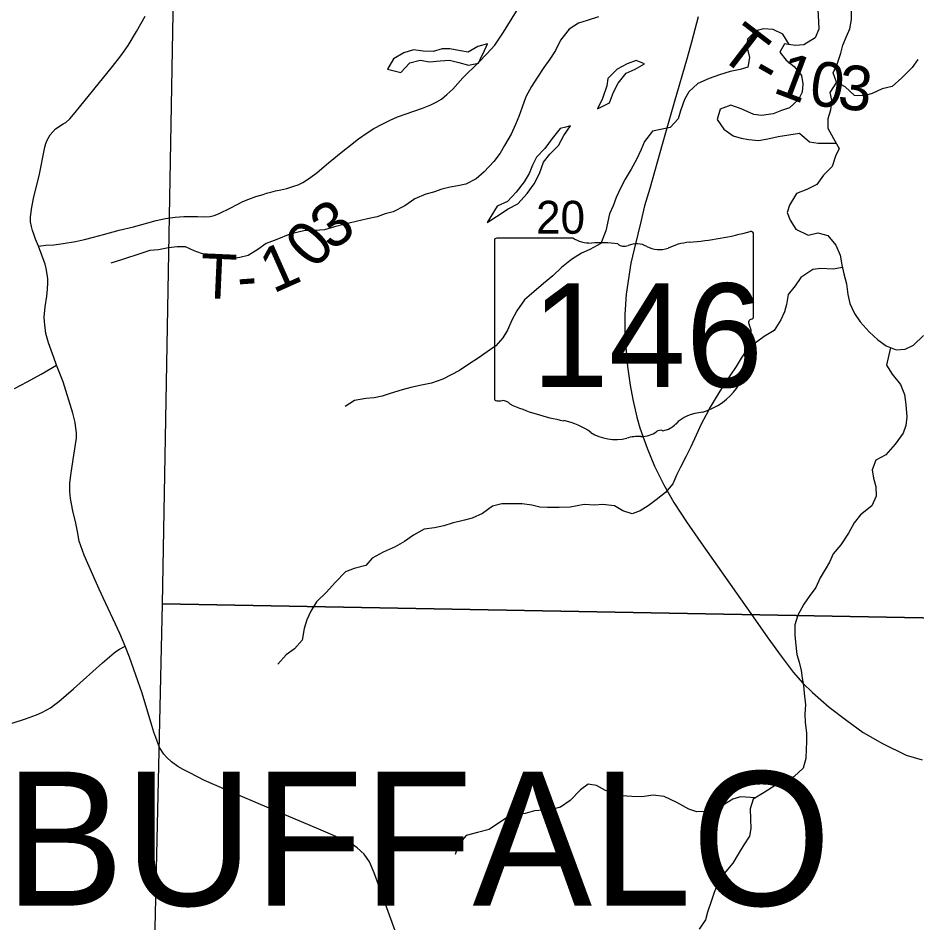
# Model space of a CAD drawing. Extents: x 0 to 34, y 0 to 22.
# Drawn here: x 27.9 to 29.042, y 16.225 to 17.376 of the extents above; entities that cross this region are included whole.
import ezdxf

# ---------------------------------------------------------------- set-up
doc = ezdxf.new("R2010")
doc.units = 0
for name, color, linetype in [('GM_X_Corporation', 7, 'Continuous'), ('GM_X_County_Road', 7, 'Continuous'), ('GM_X_Minor_Lake', 7, 'Continuous'), ('GM_X_Minor_River', 7, 'Continuous'), ('GM_X_Section_Text', 7, 'Continuous'), ('GM_X_State_Location', 7, 'Continuous'), ('GM_X_State_Route', 7, 'Continuous'), ('GM_X_State_Shield', 7, 'Continuous'), ('GM_X_Township_Road', 7, 'Continuous'), ('GM_X_Township_Road_Text', 7, 'Continuous'), ('GM_X_Township_Text', 7, 'Continuous')]:
    doc.layers.add(name, color=color, linetype=linetype)

msp = doc.modelspace()

# ---------------------------------------------------------------- linework, layer by layer
at = {"layer": 'GM_X_Corporation'}
for points in [[(28.101, 17.617), (29.1032, 17.5952), (29.0727, 16.6129), (28.0831, 16.631)], [(28.0831, 16.631), (29.0727, 16.6129), (29.0554, 15.5858), (28.0603, 15.6194)]]:
    msp.add_lwpolyline(points, close=True, dxfattribs=at)
at = {"layer": 'GM_X_County_Road'}
for points in [[(28.0356, 16.5774), (28.0289, 16.5933), (28.0203, 16.6117), (28.0079, 16.6387), (28.0027, 16.65), (27.9975, 16.6614), (27.9834, 16.6931), (27.9773, 16.7107), (27.9749, 16.723), (27.973, 16.7337), (27.9692, 16.7493), (27.9662, 16.7652), (27.9653, 16.7737), (27.9655, 16.7846), (27.9671, 16.7976), (27.9706, 16.8203), (27.9737, 16.8418), (27.9739, 16.8486), (27.9731, 16.8546), (27.9721, 16.8616), (27.9692, 16.8734), (27.9567, 16.9132), (27.9485, 16.9348), (27.9452, 16.9445), (27.9381, 16.9632), (27.9364, 16.969), (27.9349, 16.9748), (27.9334, 16.9858), (27.933, 16.99), (27.9328, 16.9955), (27.934, 17.0089), (27.9362, 17.0225), (27.937, 17.0313), (27.9373, 17.0393), (27.9373, 17.0445), (27.9364, 17.0503), (27.9353, 17.0575), (27.9338, 17.0632), (27.9254, 17.0861), (27.9217, 17.0949), (27.9196, 17.1012), (27.9179, 17.1057), (27.9166, 17.111), (27.9155, 17.1169), (27.9153, 17.1233), (27.917, 17.1354), (27.9197, 17.1485), (27.9265, 17.1755), (27.9336, 17.2119), (27.9347, 17.2164), (27.9365, 17.2208), (27.9403, 17.2273), (27.9437, 17.2312), (27.9472, 17.2352), (27.957, 17.2413), (27.9602, 17.2432), (27.9655, 17.2479), (27.9721, 17.2557), (28.0198, 17.3142), (28.0304, 17.3278), (28.0395, 17.341), (28.05, 17.359), (28.0611, 17.3783)], [(27.8919, 16.4794), (27.9088, 16.485), (27.923, 16.4901), (27.9299, 16.493), (27.9361, 16.4962), (27.9408, 16.499), (27.9446, 16.5017), (27.9514, 16.507), (27.9702, 16.5232), (28.0069, 16.5563), (28.0216, 16.5689), (28.0251, 16.5713), (28.0283, 16.5734), (28.0356, 16.5774)], [(28.3789, 16.2152), (28.3629, 16.26), (28.3524, 16.289), (28.3462, 16.3032), (28.3395, 16.3128), (28.3307, 16.321), (28.3249, 16.325), (28.3166, 16.3293), (28.2997, 16.3371), (28.2819, 16.3445), (28.2187, 16.3715), (28.1651, 16.3942), (28.1366, 16.4065), (28.1179, 16.4161), (28.1096, 16.4205), (28.1028, 16.4244), (28.0946, 16.4301), (28.0886, 16.4357), (28.0849, 16.4402), (28.0793, 16.4486), (28.0745, 16.4613), (28.0723, 16.4681), (28.0698, 16.4765), (28.0572, 16.5177), (28.0411, 16.5633), (28.0356, 16.5774)]]:
    msp.add_lwpolyline(points, dxfattribs=at)
at = {"layer": 'GM_X_Minor_Lake'}
for points in [[(28.4894, 17.3278), (28.4909, 17.3309), (28.4965, 17.343), (28.4841, 17.3396), (28.4719, 17.3324), (28.4621, 17.3344), (28.4485, 17.337), (28.4387, 17.3367), (28.4273, 17.3333), (28.4145, 17.3337), (28.4024, 17.3356), (28.3899, 17.3318), (28.377, 17.3239), (28.3694, 17.311)], [(28.3694, 17.311), (28.3861, 17.3068), (28.3978, 17.3189), (28.411, 17.3223), (28.4228, 17.3204), (28.4364, 17.3215), (28.4481, 17.3222), (28.4598, 17.3196), (28.4723, 17.3162), (28.4848, 17.3184), (28.4894, 17.3278)], [(28.6919, 17.3195), (28.6856, 17.3219), (28.6742, 17.3178), (28.6614, 17.311), (28.6496, 17.2992), (28.6481, 17.2898), (28.6428, 17.2735), (28.6363, 17.2606)], [(28.6363, 17.2606), (28.6514, 17.2682), (28.6568, 17.2818), (28.6628, 17.2932), (28.6727, 17.306), (28.6844, 17.3109), (28.6962, 17.3178), (28.6919, 17.3195)], [(28.4961, 17.116), (28.5078, 17.1236), (28.5226, 17.1334), (28.5351, 17.1398), (28.5469, 17.1527), (28.5556, 17.1652), (28.5624, 17.1781), (28.5677, 17.1928), (28.5757, 17.2027), (28.5867, 17.2137), (28.5935, 17.2265), (28.6018, 17.2387), (28.5961, 17.2373)], [(28.5961, 17.2373), (28.589, 17.2356), (28.5787, 17.2228), (28.5693, 17.2099), (28.5587, 17.1989), (28.5537, 17.1887), (28.5495, 17.1781), (28.5431, 17.1675), (28.5329, 17.1546), (28.5219, 17.1429), (28.5086, 17.1368), (28.4961, 17.116)]]:
    msp.add_lwpolyline(points, dxfattribs=at)
at = {"layer": 'GM_X_Minor_River'}
for points in [[(28.9167, 17.3864), (28.9175, 17.3717), (28.9178, 17.3618), (28.9129, 17.3508), (28.8989, 17.3417), (28.8875, 17.341), (28.8743, 17.3433), (28.8682, 17.3327), (28.8762, 17.3224), (28.8864, 17.3145), (28.8958, 17.3027), (28.8973, 17.2925), (28.8965, 17.2819), (28.892, 17.2724), (28.8806, 17.2618), (28.8704, 17.2584), (28.8598, 17.2542), (28.845, 17.252), (28.8352, 17.2535), (28.8189, 17.2607), (28.8057, 17.2653), (28.7921, 17.26), (28.7887, 17.2471), (28.797, 17.2346), (28.8087, 17.2263), (28.8189, 17.2232), (28.8287, 17.2217), (28.8412, 17.2201), (28.8529, 17.2224), (28.8661, 17.2254), (28.8798, 17.2273), (28.8934, 17.2296), (28.9058, 17.2185), (28.9168, 17.217), (28.9397, 17.217)], [(28.9404, 17.2943), (28.9359, 17.3061), (28.9416, 17.3186), (28.9458, 17.3311), (28.9484, 17.3413), (28.953, 17.3523), (28.9572, 17.3621), (28.9591, 17.3739), (28.9591, 17.3875)], [(28.6377, 17.3773), (28.6233, 17.3728), (28.6123, 17.3694), (28.6002, 17.3619), (28.5892, 17.3478), (28.5831, 17.3346), (28.5759, 17.3236), (28.568, 17.313), (28.5592, 17.2994), (28.5524, 17.2888), (28.5452, 17.2759), (28.5406, 17.2626), (28.5361, 17.2509), (28.5319, 17.2406), (28.5266, 17.2285), (28.5182, 17.2141), (28.5125, 17.2043), (28.5046, 17.1937), (28.4921, 17.1804), (28.4822, 17.1717), (28.469, 17.1649), (28.4588, 17.1627), (28.4489, 17.1608), (28.4383, 17.1585), (28.4277, 17.1544), (28.4179, 17.1521), (28.4039, 17.146), (28.3914, 17.1373), (28.3766, 17.1294), (28.3664, 17.1271), (28.3562, 17.1234), (28.3437, 17.1207), (28.315, 17.1139), (28.3021, 17.1105), (28.2892, 17.1068), (28.2775, 17.106), (28.2647, 17.1057), (28.245, 17.1012)], [(28.8802, 17.3423), (28.8721, 17.3554), (28.8596, 17.3615), (28.8475, 17.3623), (28.8377, 17.3596), (28.8271, 17.349), (28.8263, 17.3396), (28.8297, 17.3259), (28.8277, 17.3134), (28.8179, 17.3104), (28.805, 17.3081), (28.7914, 17.3036), (28.7782, 17.2991), (28.7638, 17.2926), (28.7524, 17.2821), (28.7471, 17.2722), (28.7418, 17.2578), (28.7391, 17.248), (28.7289, 17.2366), (28.7187, 17.2347), (28.7062, 17.2321), (28.6963, 17.2188), (28.6918, 17.2086), (28.6861, 17.1961), (28.6793, 17.1836), (28.6717, 17.1711), (28.666, 17.1605), (28.6599, 17.1476), (28.6561, 17.137), (28.6515, 17.1272), (28.647, 17.1054)], [(29.0437, 17.3234), (29.0365, 17.3131), (29.0232, 17.2999), (29.0111, 17.2889), (28.9982, 17.2859), (28.9857, 17.2802), (28.9759, 17.2772), (28.9631, 17.2776), (28.9514, 17.2886), (28.9404, 17.2943), (28.9317, 17.2811), (28.9339, 17.2716), (28.9328, 17.2587), (28.9293, 17.2477), (28.9293, 17.2359), (28.9365, 17.2227), (28.9436, 17.2102), (28.9391, 17.2003), (28.9349, 17.1874), (28.9239, 17.1761), (28.9152, 17.1643), (28.9027, 17.1579), (28.8895, 17.153), (28.8803, 17.1382), (28.8777, 17.1288), (28.8814, 17.1189), (28.8886, 17.1075)], [(28.8886, 17.1075), (28.904, 17.0998), (28.9164, 17.1029), (28.9293, 17.0995), (28.9396, 17.0871), (28.9449, 17.0746), (28.9472, 17.0621), (28.9495, 17.0507), (28.953, 17.0378), (28.9545, 17.0246), (28.9572, 17.0132), (28.9633, 17.0003), (28.9702, 16.9898), (28.9819, 16.9769), (28.993, 16.9667), (29.0032, 16.9592), (29.0161, 16.9543), (29.0274, 16.9551), (29.038, 16.96), (29.0509, 16.9722)], [(28.245, 17.1012), (28.2285, 17.0944), (28.2149, 17.0895), (28.2043, 17.0818), (28.1922, 17.0742), (28.1816, 17.0715), (28.1684, 17.0692), (28.1555, 17.0714), (28.1438, 17.074), (28.1328, 17.0766), (28.1233, 17.08), (28.1123, 17.0849), (28.1017, 17.0849), (28.0907, 17.0837), (28.0779, 17.0814), (28.0669, 17.0802), (28.0567, 17.0771), (28.0309, 17.0687), (28.0173, 17.0641)], [(28.647, 17.1054), (28.6405, 17.0891), (28.6265, 17.0818), (28.6159, 17.0768), (28.6034, 17.0688), (28.5906, 17.0586), (28.5796, 17.0483), (28.5675, 17.0384), (28.5555, 17.0277), (28.5434, 17.0175), (28.5339, 17.0038), (28.5275, 16.992), (28.5219, 16.9791), (28.5159, 16.9692), (28.5072, 16.9593), (28.4959, 16.9517), (28.4845, 16.9433), (28.4739, 16.9369), (28.4607, 16.9277), (28.4395, 16.917), (28.4252, 16.9117), (28.4127, 16.909), (28.3991, 16.9063), (28.3881, 16.9032), (28.3726, 16.8986), (28.3624, 16.8951), (28.3525, 16.8932), (28.3419, 16.8924), (28.3272, 16.8897), (28.3155, 16.8821)], [(28.9479, 17.0587), (28.9359, 17.0567), (28.9204, 17.0574), (28.9101, 17.0563), (28.895, 17.046), (28.8875, 17.0353), (28.8788, 17.0243), (28.8766, 17.0118), (28.8743, 17.0023), (28.8694, 16.9924), (28.8608, 16.9788), (28.8483, 16.9711), (28.8385, 16.9639), (28.8271, 16.9555), (28.8192, 16.9434), (28.8128, 16.9331), (28.8045, 16.921), (28.794, 16.905), (28.7861, 16.8917), (28.7797, 16.8811), (28.7744, 16.8716), (28.768, 16.8594), (28.762, 16.8458), (28.7552, 16.8306), (28.7488, 16.818), (28.742, 16.8051), (28.7371, 16.7956), (28.7322, 16.7839), (28.7228, 16.7725), (28.7111, 16.7633), (28.7009, 16.7557), (28.6907, 16.7496), (28.6805, 16.7454), (28.6687, 16.7495), (28.6581, 16.7556), (28.643, 16.7574), (28.6324, 16.7566), (28.6195, 16.7573), (28.6017, 16.7542), (28.5877, 16.7538), (28.5729, 16.7537), (28.5631, 16.7541), (28.5528, 16.7567), (28.5407, 16.7582), (28.5248, 16.7585), (28.5146, 16.7585), (28.5029, 16.7554), (28.49, 16.7459), (28.4768, 16.7401), (28.467, 16.7374), (28.4514, 16.7336), (28.4408, 16.7302), (28.4291, 16.7278), (28.4159, 16.7259), (28.4023, 16.7186), (28.3909, 16.7103), (28.3792, 16.7038), (28.3637, 16.6969), (28.3497, 16.6893), (28.3418, 16.6798), (28.3267, 16.6759), (28.3161, 16.6717), (28.3029, 16.6584), (28.2919, 16.6458), (28.2791, 16.6337), (28.2719, 16.6219), (28.2667, 16.6109), (28.2633, 16.5999), (28.2607, 16.5851), (28.2509, 16.5741), (28.2403, 16.5661), (28.2297, 16.5546)], [(29.0087, 16.9571), (29.004, 16.9345), (29.0109, 16.9232), (29.0215, 16.91), (29.0265, 16.8975), (29.0284, 16.8846), (29.0296, 16.8687), (29.0285, 16.8577), (29.0251, 16.8482), (29.0149, 16.8341), (29.0028, 16.8204), (28.9904, 16.8136), (28.9855, 16.8014), (28.9874, 16.7908), (28.9901, 16.7802), (28.9905, 16.7681), (28.9852, 16.7559), (28.9709, 16.7445), (28.9626, 16.7342), (28.9554, 16.721), (28.9456, 16.7061), (28.9362, 16.6947), (28.9313, 16.6841), (28.9257, 16.6746), (28.9196, 16.6644), (28.914, 16.6518), (28.9053, 16.6404), (28.8985, 16.6309), (28.891, 16.6169), (28.8872, 16.6044), (28.8873, 16.5918), (28.8881, 16.5824), (28.89, 16.5668), (28.8927, 16.557), (28.8954, 16.5464), (28.8965, 16.5365), (28.8981, 16.5271), (28.8992, 16.5176), (28.9008, 16.5028), (28.9001, 16.4914), (28.9005, 16.4804), (28.902, 16.4672), (28.9021, 16.4558), (28.9017, 16.4463), (28.9014, 16.4346), (28.898, 16.4224), (28.8863, 16.4114), (28.8753, 16.4061), (28.8636, 16.4011), (28.8481, 16.3912), (28.8341, 16.3828), (28.8304, 16.3703), (28.8308, 16.3574), (28.8312, 16.3453), (28.8297, 16.3358), (28.8222, 16.3248), (28.815, 16.313), (28.8086, 16.3016), (28.7973, 16.2883), (28.7894, 16.2761), (28.7845, 16.264), (28.7811, 16.2541), (28.7762, 16.2393), (28.7736, 16.2294), (28.7657, 16.2177)], [(28.8371, 16.3846), (28.8182, 16.3858), (28.8084, 16.3827), (28.7974, 16.3762), (28.7861, 16.3713), (28.7732, 16.367), (28.7626, 16.3666), (28.7524, 16.37), (28.7372, 16.3787), (28.7209, 16.3862), (28.7073, 16.388), (28.6925, 16.3857), (28.68, 16.386), (28.6671, 16.3871), (28.6573, 16.3894), (28.6463, 16.3939), (28.6349, 16.4003), (28.6243, 16.4018), (28.6145, 16.3945), (28.6017, 16.3812), (28.5892, 16.3728), (28.5794, 16.3702), (28.5672, 16.3686), (28.5563, 16.3678), (28.5445, 16.3647), (28.5313, 16.3635), (28.5203, 16.3586), (28.5105, 16.3521), (28.4984, 16.3441), (28.4837, 16.3402), (28.4693, 16.3364), (28.4595, 16.325), (28.4553, 16.3125)]]:
    msp.add_lwpolyline(points, dxfattribs=at)
at = {"layer": 'GM_X_State_Route'}
msp.add_lwpolyline([(28.7643, 17.3775), (28.756, 17.3452), (28.7502, 17.3255), (28.7338, 17.2687), (28.7184, 17.2153), (28.7028, 17.1593), (28.6961, 17.137), (28.6914, 17.117), (28.6875, 17.1012), (28.6831, 17.082), (28.6788, 17.0644), (28.6727, 17.0247), (28.6711, 16.9992), (28.6709, 16.9729), (28.6746, 16.9328), (28.678, 16.9092), (28.6813, 16.8909), (28.6864, 16.8686), (28.6902, 16.855), (28.6993, 16.8292), (28.7089, 16.8061), (28.7207, 16.7826), (28.7336, 16.7599), (28.7494, 16.7356), (28.7678, 16.7093), (28.8341, 16.6148), (28.8529, 16.5881), (28.8699, 16.5646), (28.8852, 16.5444), (28.8974, 16.5304), (28.9099, 16.5184), (28.931, 16.4999), (28.9534, 16.4828), (28.9741, 16.4677), (28.9987, 16.4537), (29.029, 16.4389), (29.0493, 16.4326)], dxfattribs=at)
at = {"layer": 'GM_X_State_Shield'}
for p, q in [((28.605, 17.0962), (28.5085, 17.0962)), ((28.8348, 16.9965), (28.8348, 17.1012)), ((28.5052, 17.0928), (28.5052, 16.8927)), ((28.8348, 16.9965), (28.8348, 16.9965))]:
    msp.add_line(p, q, dxfattribs=at)
for centre, major_axis, start_param, end_param in [((28.509, 17.0932), (0.00382, 0), 1.712693, 3.28349), ((28.628, 17.1195), (0.037, 0), 4.042523, 4.731795), ((28.7174, 17.3691), (0.3495, 0), 4.814394, 5.042369), ((28.8311, 17.1016), (0.00367, 0), 6.141152, 7.989035), ((28.6402, 16.9839), (0.133, 0), 1.404758, 1.657858), ((28.6704, 17.0943), (0.0107, 0), 3.836095, 5.185415), ((28.6861, 17.0711), (0.0222, 0), 0.950623, 2.079405), ((28.7148, 17.1029), (0.0267, 0), 4.081561, 5.145723), ((28.762, 17.0351), (0.0703, 0), 1.699011, 2.107814), ((28.834, 16.9888), (0.00568, 0), 1.883978, 3.671073), ((28.8309, 16.9961), (0.00393, 0), 5.05454, 6.418171), ((28.7978, 16.9756), (0.0341, 0), 5.934695, 6.695948), ((28.8479, 16.9527), (0.0248, 0), 2.387724, 3.262537), ((28.737, 16.9394), (0.0874, 0), 5.101752, 6.440018), ((28.509, 16.8922), (0.00385, 0), 3.00124, 4.508301), ((28.5096, 16.9127), (0.0294, 0), 4.665946, 4.897461), ((28.5156, 16.8811), (0.0106, 0), 0.519207, 1.627899), ((28.6494, 17.0609), (0.2524, 0), 4.195997, 4.488961), ((28.7738, 16.8365), (0.0479, 0), 1.647645, 2.488434), ((28.5742, 16.8028), (0.079, 0), 0.823519, 1.323587), ((28.7132, 16.8733), (0.0282, 0), 4.937069, 5.64225), ((28.6596, 16.8801), (0.0501, 0), 4.026481, 4.996735), ((28.6886, 16.811), (0.0412, 0), 1.495662, 1.94098), ((28.6922, 16.8652), (0.0267, 0), 4.691044, 5.507374), ((28.7164, 16.8458), (0.00752, 0), 1.147584, 2.315152)]:
    msp.add_ellipse(centre, major_axis=major_axis, ratio=0.8, start_param=start_param, end_param=end_param, dxfattribs=at)
at = {"layer": 'GM_X_Township_Road'}
for points in [[(27.9254, 17.0861), (27.935, 17.087), (27.9449, 17.0877), (27.9569, 17.0894), (27.9726, 17.0919), (27.9839, 17.0943), (27.9953, 17.0972), (28.008, 17.1006), (28.0281, 17.1062), (28.0463, 17.1105), (28.0752, 17.1185), (28.0872, 17.1211), (28.0992, 17.1229), (28.1103, 17.1236), (28.1278, 17.1236), (28.1355, 17.1234), (28.1439, 17.1237), (28.1487, 17.1247), (28.1544, 17.1269), (28.1702, 17.1348), (28.1855, 17.1425), (28.193, 17.1457), (28.2019, 17.149), (28.211, 17.1518), (28.2156, 17.1532), (28.221, 17.1547), (28.227, 17.1563), (28.2338, 17.1577), (28.2411, 17.1594), (28.25, 17.162), (28.2555, 17.1639), (28.2616, 17.1669), (28.2703, 17.1722), (28.28, 17.1797), (28.2941, 17.1918), (28.3126, 17.2066), (28.3221, 17.2142), (28.3326, 17.2223), (28.3421, 17.229), (28.352, 17.2353), (28.3626, 17.2412), (28.3727, 17.2463), (28.3822, 17.2502), (28.4027, 17.2577), (28.4136, 17.2615), (28.4243, 17.2656), (28.4319, 17.2693), (28.4378, 17.2728), (28.4449, 17.2786), (28.4522, 17.2855), (28.4587, 17.2926), (28.4652, 17.2999), (28.4854, 17.32), (28.4956, 17.3306), (28.5056, 17.3416), (28.511, 17.3489), (28.517, 17.3578), (28.5387, 17.3935)], [(27.8951, 16.9049), (27.9113, 16.9136), (27.9287, 16.9232), (27.9485, 16.9348)]]:
    msp.add_lwpolyline(points, dxfattribs=at)

# ---------------------------------------------------------------- texts
at = {"layer": 'GM_X_Section_Text'}
msp.add_text('20', height=0.04186, rotation=0, dxfattribs=at).set_placement((28.5582, 17.1017))
at = {"layer": 'GM_X_State_Location'}
for s in ['s', 'r']:
    msp.add_text(s, height=0.000189, dxfattribs=at).set_placement((28.6663, 16.9794))
msp.add_text('146', height=0.000189, rotation=0, dxfattribs=at).set_placement((28.5994, 16.9657))
at = {"layer": 'GM_X_State_Shield'}
msp.add_text('146', height=0.13184, dxfattribs=at).set_placement((28.5526, 16.9068))
at = {"layer": 'GM_X_Township_Road_Text'}
for s, rotation, p in [('T', 322.5678, (28.7881, 17.3282)), ('1', 339.251, (28.8578, 17.282)), ('-', 330.2947, (28.8288, 17.2977)), ('0', 352.1511, (28.904, 17.2662)), ('3', 353.6434, (28.9403, 17.2612)), ('3', 35.4282, (28.2976, 17.0787)), ('0', 48.1782, (28.2768, 17.0548)), ('1', 24.044, (28.2239, 17.0253)), ('T', 357.4192, (28.1301, 17.0202)), ('-', 4.0323, (28.1797, 17.0184))]:
    msp.add_text(s, height=0.0568, rotation=rotation, dxfattribs=at).set_placement(p)
at = {"layer": 'GM_X_Township_Text'}
msp.add_text('BUFFALO', height=0.17045, rotation=0, dxfattribs=at).set_placement((27.8823, 16.2474))

doc.saveas('drawing.dxf')
